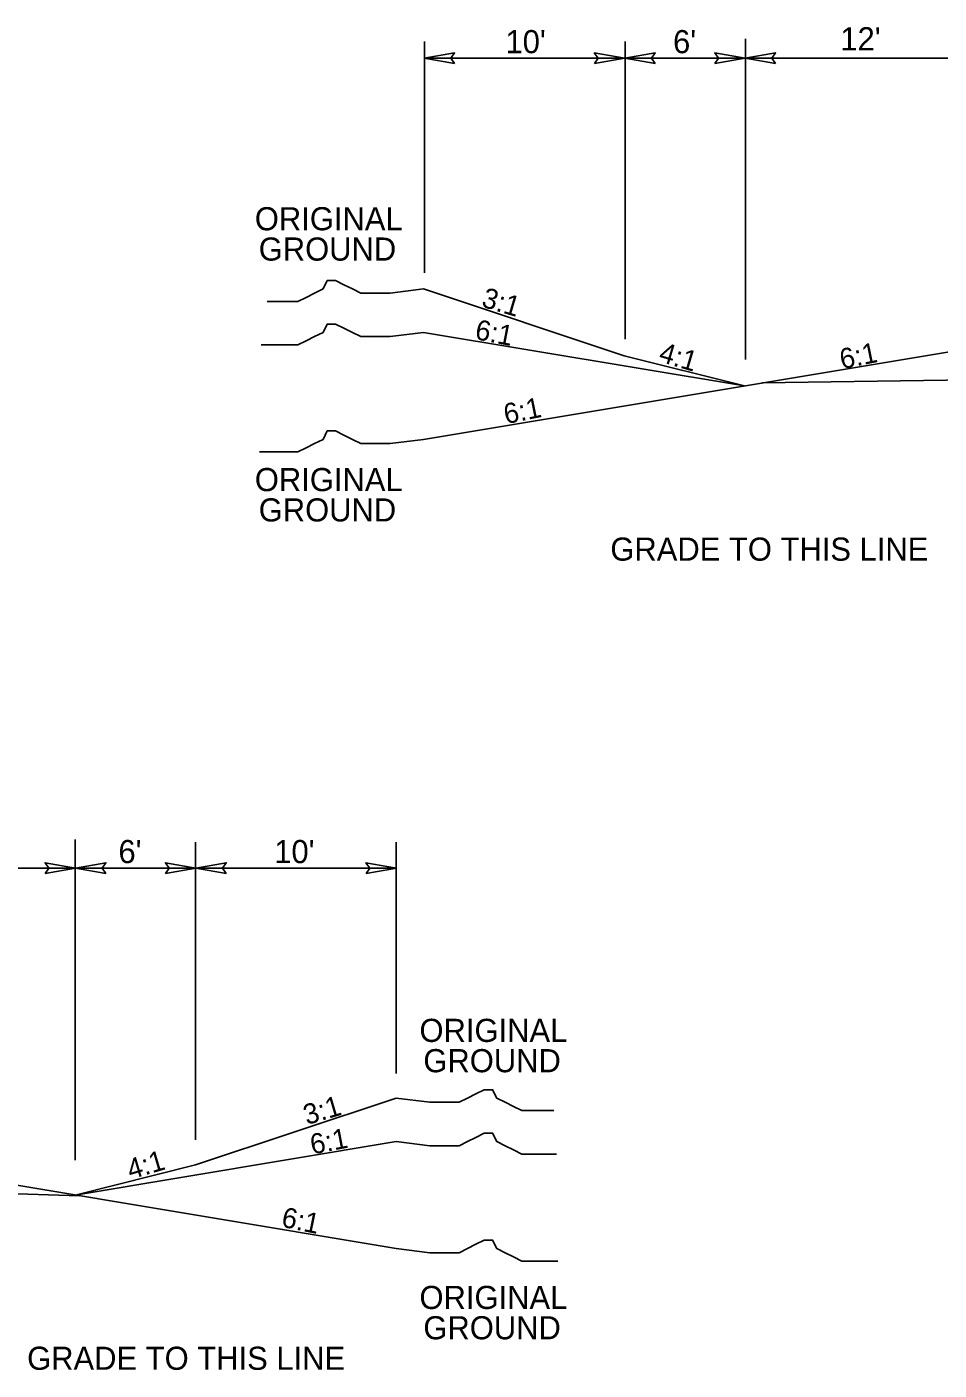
# Model space of a CAD drawing. Extents: x 2176156 to 2177167, y 76401 to 76644.
# Drawn here: x 2177029.7 to 2177075.2, y 76463.3 to 76530.3 of the extents above; entities that cross this region are included whole.
import ezdxf

# ---------------------------------------------------------------- set-up
doc = ezdxf.new("R2010")
doc.units = 0
for name, color, linetype in [('Exist Building', 7, 'Continuous'), ('Exist Roads Curbs', 7, 'Continuous'), ('Exist Roads EOP Other', 7, 'Continuous'), ('Exist Roads Soil', 7, 'Continuous'), ('Exist Structure Minor Culvert Topo', 7, 'Continuous'), ('Old_Level_1', 7, 'Continuous'), ('Old_Level_3', 7, 'Continuous')]:
    doc.layers.add(name, color=color, linetype=linetype)

msp = doc.modelspace()

# ---------------------------------------------------------------- linework, layer by layer
at = {"layer": 'Exist Building'}
for p, q in [((2177066.344, 76512.553), (2177091.306, 76512.924)), ((2177032.311, 76472.018), (2176998.106, 76473.085))]:
    msp.add_line(p, q, dxfattribs=at)
at = {"layer": 'Exist Roads Curbs'}
for points in [[(2177049.46, 76517.239), (2177047.789, 76517.031), (2177047.371, 76517.031), (2177046.744, 76517.031), (2177046.326, 76517.031), (2177045.909, 76517.239), (2177045.491, 76517.448), (2177045.073, 76517.658), (2177044.656, 76517.658), (2177044.446, 76517.239), (2177044.028, 76517.031), (2177043.611, 76516.821), (2177043.193, 76516.613), (2177042.775, 76516.613), (2177042.358, 76516.613), (2177041.94, 76516.613), (2177041.669, 76516.613)], [(2177049.459, 76515.072), (2177047.789, 76514.864), (2177047.371, 76514.864), (2177046.744, 76514.864), (2177046.326, 76514.864), (2177045.909, 76515.072), (2177045.491, 76515.282), (2177045.073, 76515.491), (2177044.656, 76515.491), (2177044.446, 76515.072), (2177044.028, 76514.864), (2177043.611, 76514.654), (2177043.193, 76514.446), (2177042.775, 76514.446), (2177042.358, 76514.446), (2177041.94, 76514.446), (2177041.522, 76514.446), (2177041.359, 76514.446)], [(2177049.46, 76509.739), (2177047.789, 76509.531), (2177047.371, 76509.531), (2177046.744, 76509.531), (2177046.326, 76509.531), (2177045.909, 76509.739), (2177045.491, 76509.948), (2177045.073, 76510.158), (2177044.656, 76510.158), (2177044.446, 76509.739), (2177044.028, 76509.531), (2177043.611, 76509.321), (2177043.193, 76509.113), (2177042.775, 76509.113), (2177042.358, 76509.113), (2177041.94, 76509.113), (2177041.523, 76509.113), (2177041.282, 76509.113)], [(2177048.093, 76476.888), (2177049.764, 76476.68), (2177050.182, 76476.68), (2177050.809, 76476.68), (2177051.227, 76476.68), (2177051.644, 76476.888), (2177052.062, 76477.097), (2177052.479, 76477.307), (2177052.897, 76477.307), (2177053.107, 76476.888), (2177053.524, 76476.68), (2177053.942, 76476.47), (2177054.36, 76476.262), (2177054.777, 76476.262), (2177055.195, 76476.262), (2177055.613, 76476.262), (2177055.952, 76476.262)], [(2177048.093, 76474.721), (2177049.764, 76474.513), (2177050.182, 76474.513), (2177050.809, 76474.513), (2177051.227, 76474.513), (2177051.644, 76474.721), (2177052.062, 76474.931), (2177052.48, 76475.14), (2177052.897, 76475.14), (2177053.107, 76474.721), (2177053.525, 76474.513), (2177053.942, 76474.303), (2177054.36, 76474.095), (2177054.778, 76474.095), (2177055.195, 76474.095), (2177055.613, 76474.095), (2177056.031, 76474.095), (2177056.078, 76474.095)], [(2177048.093, 76469.388), (2177049.764, 76469.18), (2177050.182, 76469.18), (2177050.809, 76469.18), (2177051.227, 76469.18), (2177051.644, 76469.388), (2177052.062, 76469.597), (2177052.479, 76469.807), (2177052.897, 76469.807), (2177053.107, 76469.388), (2177053.524, 76469.18), (2177053.942, 76468.97), (2177054.36, 76468.762), (2177054.777, 76468.762), (2177055.195, 76468.762), (2177055.613, 76468.762), (2177056.03, 76468.762), (2177056.154, 76468.762)]]:
    msp.add_lwpolyline(points, dxfattribs=at)
at = {"layer": 'Exist Roads EOP Other'}
for p, q in [((2177059.46, 76513.905), (2177049.46, 76517.239)), ((2177065.46, 76512.405), (2177059.46, 76513.905)), ((2177038.093, 76473.554), (2177048.093, 76476.888)), ((2177032.093, 76472.054), (2177038.093, 76473.554))]:
    msp.add_line(p, q, dxfattribs=at)
at = {"layer": 'Exist Roads Soil'}
for p, q in [((2177065.46, 76512.405), (2177049.46, 76515.072)), ((2177049.46, 76509.739), (2177077.412, 76514.397)), ((2177032.093, 76472.054), (2177048.093, 76474.721)), ((2177048.093, 76469.388), (2177020.141, 76474.046))]:
    msp.add_line(p, q, dxfattribs=at)
at = {"layer": 'Old_Level_1'}
for points in [[(2177050.998, 76528.484), (2177049.488, 76528.744), (2177051.006, 76529.012), (2177050.813, 76528.744)], [(2177057.979, 76528.484), (2177059.488, 76528.744), (2177057.97, 76529.012), (2177058.163, 76528.744)], [(2177060.998, 76528.484), (2177059.488, 76528.744), (2177061.006, 76529.012), (2177060.813, 76528.744)], [(2177063.979, 76528.484), (2177065.488, 76528.744), (2177063.97, 76529.012), (2177064.163, 76528.744)], [(2177066.998, 76528.484), (2177065.488, 76528.744), (2177067.006, 76529.012), (2177066.813, 76528.744)], [(2177030.596, 76488.094), (2177032.106, 76488.354), (2177030.588, 76488.622), (2177030.781, 76488.354)], [(2177033.616, 76488.094), (2177032.106, 76488.354), (2177033.624, 76488.622), (2177033.431, 76488.354)], [(2177036.596, 76488.094), (2177038.106, 76488.354), (2177036.588, 76488.622), (2177036.781, 76488.354)], [(2177039.616, 76488.094), (2177038.106, 76488.354), (2177039.624, 76488.622), (2177039.431, 76488.354)], [(2177046.596, 76488.094), (2177048.106, 76488.354), (2177046.588, 76488.622), (2177046.781, 76488.354)]]:
    msp.add_lwpolyline(points, close=True, dxfattribs=at)
at = {"layer": 'Old_Level_3'}
for p, q in [((2177049.501, 76518.036), (2177049.501, 76529.576)), ((2177059.501, 76514.734), (2177059.501, 76529.576)), ((2177065.501, 76513.717), (2177065.501, 76529.71)), ((2177059.488, 76528.744), (2177049.488, 76528.744)), ((2177065.488, 76528.744), (2177059.488, 76528.744)), ((2177077.488, 76528.744), (2177065.488, 76528.744)), ((2177032.093, 76473.794), (2177032.093, 76489.787)), ((2177038.093, 76474.812), (2177038.093, 76489.654)), ((2177048.093, 76478.114), (2177048.093, 76489.654)), ((2177020.106, 76488.354), (2177032.106, 76488.354)), ((2177032.106, 76488.354), (2177038.106, 76488.354)), ((2177038.106, 76488.354), (2177048.106, 76488.354))]:
    msp.add_line(p, q, dxfattribs=at)

# ---------------------------------------------------------------- texts
at = {"layer": 'Exist Roads Curbs'}
for s, rotation, p in [('3:1', 343.53506, (2177052.295, 76516.371)), ('6:1', 349.18318, (2177051.976, 76514.744)), ('4:1', 343.53506, (2177061.127, 76513.639)), ('6:1', 11.48655, (2177070.312, 76513.235)), ('6:1', 11.48655, (2177053.562, 76510.494)), ('3:1', 16.46494, (2177043.64, 76475.542)), ('6:1', 10.81682, (2177043.907, 76474.073)), ('4:1', 16.46494, (2177034.85, 76472.822)), ('6:1', 348.51345, (2177042.325, 76470.482))]:
    msp.add_text(s, height=1.0064, rotation=rotation, dxfattribs=at).set_placement(p)
at = {"layer": 'Exist Structure Minor Culvert Topo'}
for s, height, p in [("10'", 1.1533, (2177053.541, 76528.996)), ("6'", 1.1533, (2177061.895, 76528.996)), ("12' ", 1.1533, (2177070.234, 76529.139)), ('ORIGINAL', 1.1533, (2177041.046, 76520.165)), ('GROUND', 1.1533, (2177041.24, 76518.653)), ('ORIGINAL', 1.1533, (2177041.046, 76507.157)), ('GROUND', 1.1533, (2177041.24, 76505.645)), ('GRADE TO THIS LINE', 1.15334, (2177058.768, 76503.689)), ("6'", 1.1533, (2177034.248, 76488.606)), ("10'", 1.1533, (2177042.014, 76488.606)), ('ORIGINAL', 1.1533, (2177049.253, 76479.689)), ('GROUND', 1.1533, (2177049.447, 76478.178)), ('ORIGINAL', 1.1533, (2177049.253, 76466.371)), ('GROUND', 1.1533, (2177049.447, 76464.859)), ('GRADE TO THIS LINE', 1.15334, (2177029.695, 76463.338))]:
    msp.add_text(s, height=height, dxfattribs=at).set_placement(p)

doc.saveas('drawing.dxf')
